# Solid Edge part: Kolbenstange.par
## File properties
Username: ahadarics
Dokumentum tartalom típus: 0
Author: ahadarics
Last saved by: ahadarics
Revision: 78
Sűrűség: 0,000 kg/m^3
Pontosság: 0,990
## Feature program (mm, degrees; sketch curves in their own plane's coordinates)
base feature "unnamed BaseFeature 1"
sketch for "Furat_1" plane through (-10, 0, 0) normal (-1, 0, 0) x-axis (0, 1, 0)
  hole centre (0, 0) bore radius 4.188
hole "Furat_1" nominal diameter 10 finite  ThreadDepth = 17 mm
sketch for "Kihúzás_1" plane through (48.25, 0, 0) normal (1, 0, 0) x-axis (0, -1, 0)
  circle centre (0, 0) radius 31.5
extrude "Kihúzás_1" add finite 21.5 along -normal
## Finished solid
Body 1: solid body, 15 faces, 21 edges, 8 vertices.
  Faces by surface: plane 8, cylinder 4, cone 2, torus 1
  Edges by curve: circle 11, line 6, ellipse 2, intersection 2
Bounding box of the edges (mm; curved faces can reach further): 58.250 x 63.000 x 63.000, from (-10, -31.5, -31.5) to (48.25, 31.5, 31.5).
Cylindrical faces by radius (mm): R4.185 x1, R4.188 x1, R8 x1, R31.5 x1
Conical faces (half-angle, radius in mm at the cone's reference point): 45 deg R4.185 x1, 59 deg R2.094 x1
Toroidal faces (ring radius, tube radius in mm): R6.3 r1.7 x1
Planar faces by outward normal: +x 1, +z 1, -x 3, -z 1, oblique 2
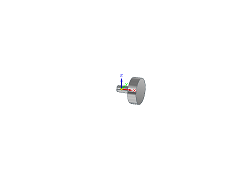
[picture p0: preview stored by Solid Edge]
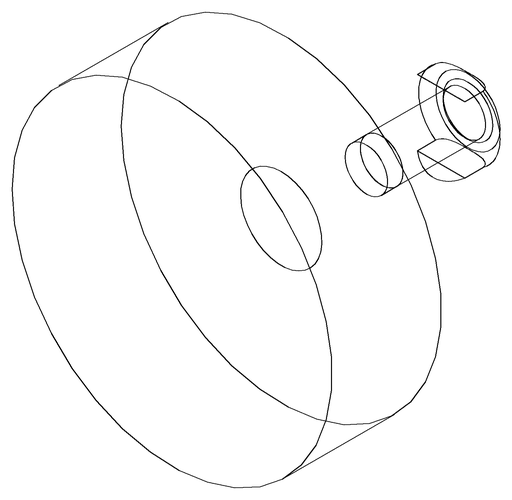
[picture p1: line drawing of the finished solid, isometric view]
